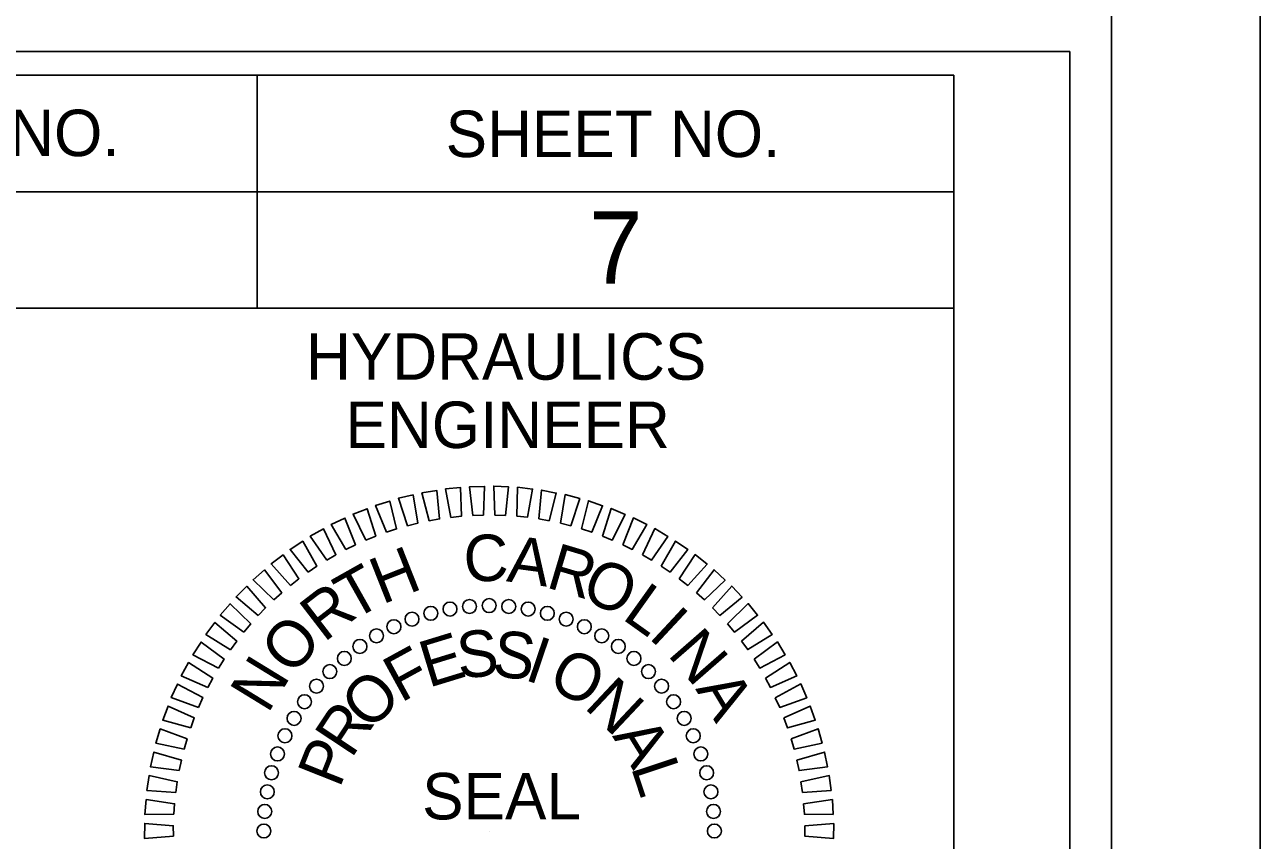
# Model space of a CAD drawing. Extents: x 1633303 to 1635397, y 883210 to 885302.
# Drawn here: x 1635263.8 to 1635396.9, y 884890.3 to 884978 of the extents above; entities that cross this region are included whole.
import ezdxf

# ---------------------------------------------------------------- set-up
doc = ezdxf.new("R2010")
doc.units = 0
for name, color, linetype in [('Sheet Data Field CELL', 7, 'Continuous'), ('Sheet PE Seal Cell', 7, 'Continuous'), ('Sheet Plot Border Inside CELL', 7, 'Continuous'), ('Sheet Plot Border Outside CELL', 7, 'Continuous'), ('Sheet Profile CELL', 7, 'Continuous'), ('Stewart Plot Border Xerox6279 and LJ5000', 7, 'Continuous')]:
    doc.layers.add(name, color=color, linetype=linetype)

msp = doc.modelspace()

# ---------------------------------------------------------------- linework, layer by layer
at = {"layer": 'Sheet PE Seal Cell'}
msp.add_line((1635313.84, 884891.31), (1635313.84, 884891.31), dxfattribs=at)
for points in [[(1635309.72, 884925.05), (1635309.16, 884928.12), (1635310.77, 884928.26), (1635310.85, 884925.17)], [(1635312.08, 884925.25), (1635311.74, 884928.35), (1635313.35, 884928.38), (1635313.22, 884925.3)], [(1635314.45, 884925.29), (1635314.33, 884928.41), (1635315.94, 884928.33), (1635315.6, 884925.26)], [(1635316.82, 884925.17), (1635316.91, 884928.29), (1635318.52, 884928.09), (1635317.96, 884925.06)], [(1635302.79, 884923.45), (1635301.61, 884926.34), (1635303.15, 884926.81), (1635303.88, 884923.81)], [(1635305.06, 884924.15), (1635304.08, 884927.11), (1635305.66, 884927.47), (1635306.17, 884924.43)], [(1635307.38, 884924.68), (1635306.6, 884927.7), (1635308.2, 884927.95), (1635308.5, 884924.88)], [(1635319.18, 884924.88), (1635319.49, 884927.98), (1635321.07, 884927.67), (1635320.3, 884924.69)], [(1635321.51, 884924.42), (1635322.03, 884927.5), (1635323.59, 884927.08), (1635322.62, 884924.15)], [(1635323.8, 884923.81), (1635324.53, 884926.84), (1635326.06, 884926.31), (1635324.89, 884923.46)], [(1635300.58, 884922.61), (1635299.19, 884925.4), (1635300.7, 884925.98), (1635301.63, 884923.04)], [(1635326.04, 884923.03), (1635326.99, 884926.01), (1635328.47, 884925.37), (1635327.1, 884922.61)], [(1635298.43, 884921.6), (1635296.85, 884924.3), (1635298.32, 884924.98), (1635299.45, 884922.11)], [(1635328.22, 884922.1), (1635329.38, 884925), (1635330.82, 884924.27), (1635329.25, 884921.61)], [(1635296.35, 884920.46), (1635294.59, 884923.03), (1635296, 884923.82), (1635297.34, 884921.03)], [(1635330.34, 884921.03), (1635331.69, 884923.84), (1635333.07, 884923.01), (1635331.33, 884920.46)], [(1635294.36, 884919.16), (1635292.42, 884921.61), (1635293.78, 884922.49), (1635295.3, 884919.81)], [(1635332.37, 884919.8), (1635333.91, 884922.51), (1635335.24, 884921.59), (1635333.32, 884919.17)], [(1635292.47, 884917.74), (1635290.36, 884920.04), (1635291.65, 884921.02), (1635293.36, 884918.45)], [(1635334.31, 884918.44), (1635336.04, 884921.04), (1635337.3, 884920.02), (1635335.22, 884917.74)], [(1635290.67, 884916.18), (1635288.42, 884918.34), (1635289.64, 884919.4), (1635291.52, 884916.95)], [(1635336.16, 884916.95), (1635338.06, 884919.42), (1635339.24, 884918.31), (1635337.01, 884916.19)], [(1635288.99, 884914.51), (1635286.59, 884916.5), (1635287.74, 884917.64), (1635289.78, 884915.33)], [(1635337.89, 884915.33), (1635339.96, 884917.66), (1635341.07, 884916.48), (1635338.69, 884914.51)], [(1635287.44, 884912.72), (1635284.9, 884914.54), (1635285.96, 884915.76), (1635288.17, 884913.6)], [(1635339.51, 884913.59), (1635341.74, 884915.77), (1635342.75, 884914.52), (1635340.25, 884912.72)], [(1635286.01, 884910.82), (1635283.35, 884912.46), (1635284.32, 884913.75), (1635286.67, 884911.75)], [(1635341, 884911.75), (1635343.38, 884913.77), (1635344.3, 884912.44), (1635341.68, 884910.83)], [(1635284.71, 884908.83), (1635281.95, 884910.28), (1635282.83, 884911.64), (1635285.31, 884909.81)], [(1635342.36, 884909.8), (1635344.87, 884911.65), (1635345.7, 884910.27), (1635342.97, 884908.84)], [(1635283.56, 884906.76), (1635280.7, 884908.01), (1635281.49, 884909.43), (1635284.09, 884907.77)], [(1635343.58, 884907.77), (1635346.21, 884909.44), (1635346.95, 884908), (1635344.12, 884906.76)], [(1635282.56, 884904.61), (1635279.62, 884905.66), (1635280.3, 884907.12), (1635283.02, 884905.66)], [(1635344.65, 884905.65), (1635347.4, 884907.13), (1635348.03, 884905.65), (1635345.13, 884904.61)], [(1635281.71, 884902.4), (1635278.7, 884903.24), (1635279.28, 884904.75), (1635282.09, 884903.47)], [(1635345.58, 884903.47), (1635348.42, 884904.75), (1635348.95, 884903.23), (1635345.98, 884902.4)], [(1635281.01, 884900.13), (1635277.96, 884900.76), (1635278.43, 884902.3), (1635281.32, 884901.23)], [(1635346.35, 884901.22), (1635349.28, 884902.31), (1635349.69, 884900.75), (1635346.67, 884900.13)], [(1635280.48, 884897.82), (1635277.38, 884898.23), (1635277.75, 884899.81), (1635280.71, 884898.94)], [(1635346.96, 884898.93), (1635349.96, 884899.81), (1635350.27, 884898.22), (1635347.21, 884897.82)], [(1635280.1, 884895.47), (1635276.99, 884895.67), (1635277.24, 884897.27), (1635280.26, 884896.61)], [(1635347.41, 884896.6), (1635350.46, 884897.27), (1635350.66, 884895.67), (1635347.58, 884895.47)], [(1635279.9, 884893.11), (1635276.77, 884893.09), (1635276.92, 884894.7), (1635279.97, 884894.25)], [(1635347.7, 884894.25), (1635350.79, 884894.7), (1635350.87, 884893.09), (1635347.79, 884893.11)], [(1635279.85, 884890.74), (1635276.74, 884890.5), (1635276.77, 884892.12), (1635279.84, 884891.88)], [(1635347.82, 884891.88), (1635350.94, 884892.11), (1635350.91, 884890.5), (1635347.83, 884890.74)]]:
    msp.add_lwpolyline(points, close=True, dxfattribs=at)
for centre in [(1635311.72, 884915.47), (1635313.84, 884915.56), (1635315.95, 884915.47), (1635305.54, 884914.1), (1635307.56, 884914.73), (1635309.63, 884915.19), (1635318.05, 884915.19), (1635320.11, 884914.73), (1635322.13, 884914.1), (1635303.59, 884913.29), (1635324.09, 884913.29), (1635301.71, 884912.31), (1635325.96, 884912.31), (1635299.93, 884911.17), (1635327.75, 884911.17), (1635298.25, 884909.88), (1635329.43, 884909.88), (1635296.69, 884908.46), (1635330.99, 884908.46), (1635295.26, 884906.9), (1635332.41, 884906.9), (1635293.97, 884905.22), (1635333.7, 884905.22), (1635292.84, 884903.43), (1635334.84, 884903.43), (1635291.86, 884901.56), (1635335.82, 884901.56), (1635291.05, 884899.6), (1635336.63, 884899.6), (1635290.41, 884897.58), (1635337.26, 884897.58), (1635289.96, 884895.52), (1635337.72, 884895.52), (1635289.68, 884893.42), (1635338, 884893.42), (1635289.59, 884891.31), (1635338.09, 884891.31)]:
    msp.add_circle(centre, 0.75, dxfattribs=at)
at = {"layer": 'Sheet Plot Border Inside CELL'}
msp.add_lwpolyline([(1635376.36, 884975.16), (1633709.86, 884975.16), (1633709.86, 883920.06), (1635376.36, 883920.06)], close=True, dxfattribs=at)
at = {"layer": 'Sheet Plot Border Outside CELL'}
msp.add_lwpolyline([(1635380.86, 884997.61), (1633696.86, 884997.61), (1633696.86, 883897.61), (1635380.86, 883897.61)], close=True, dxfattribs=at)
at = {"layer": 'Sheet Profile CELL'}
for p, q in [((1635288.86, 884972.56), (1635288.86, 884947.56)), ((1635163.81, 884960.06), (1635363.86, 884960.06)), ((1635263.86, 884947.56), (1635363.86, 884947.56)), ((1635363.86, 884947.56), (1635363.86, 884835.06))]:
    msp.add_line(p, q, dxfattribs=at)
for points in [[(1635363.86, 884972.61), (1633863.86, 884972.61), (1633863.86, 883922.61), (1635363.86, 883922.61)], [(1635163.81, 884972.61), (1635363.86, 884972.61), (1635363.86, 884947.56), (1635163.81, 884947.56)]]:
    msp.add_lwpolyline(points, close=True, dxfattribs=at)
at = {"layer": 'Stewart Plot Border Xerox6279 and LJ5000'}
msp.add_lwpolyline([(1633696.86, 883897.61), (1635396.86, 883897.61), (1635396.86, 884997.61), (1633696.86, 884997.61)], close=True, dxfattribs=at)

# ---------------------------------------------------------------- texts
at = {"layer": 'Sheet Data Field CELL'}
msp.add_text('7', height=7.75, dxfattribs=at).set_placement((1635324.6, 884950.21))
at = {"layer": 'Sheet PE Seal Cell'}
for s, rotation, p in [('C', 1.9618, (1635311.17, 884918.11)), ('A', 352.4568, (1635315.63, 884918.18)), ('H', 21.601, (1635302.32, 884915.65)), ('R', 343.4093, (1635319.83, 884917.56)), ('T', 29.3903, (1635299.12, 884913.87)), ('O', 335.2006, (1635323.52, 884916.44)), ('R', 37.5989, (1635296.05, 884911.53)), ('L', 324.4755, (1635328.03, 884914.2)), ('I', 317.0103, (1635330.88, 884912.16)), ('O', 48.3241, (1635292.6, 884907.87)), ('E', 16.986, (1635307.31, 884906.7)), ('S', 5.2237, (1635310.58, 884907.7)), ('S', 353.2648, (1635314.05, 884908.02)), ('I', 341.3058, (1635317.51, 884907.62)), ('N', 311.0704, (1635332.95, 884910.28)), ('F', 28.6639, (1635304.33, 884905.06)), ('N', 58.5345, (1635290, 884903.84)), ('O', 332.5504, (1635319.95, 884906.87)), ('O', 44.4727, (1635300.94, 884901.95)), ('N', 316.7416, (1635323.96, 884904.61)), ('A', 300.8599, (1635336.01, 884906.6)), ('R', 56.5721, (1635299, 884899.01)), ('A', 301.6915, (1635327.06, 884901.53)), ('P', 68.3344, (1635297.74, 884895.82)), ('L', 288.3556, (1635329.07, 884898.2))]:
    msp.add_text(s, height=5, rotation=rotation, dxfattribs=at).set_placement(p)
msp.add_text('SEAL', height=5, dxfattribs=at).set_placement((1635306.63, 884892.56))
at = {"layer": 'Sheet Profile CELL'}
for s, height, p in [('PROJECT REFERENCE NO.', 5.0001, (1635186.01, 884963.91)), ('SHEET NO.', 5, (1635309.16, 884963.81)), ('HYDRAULICS', 5, (1635294.13, 884939.86)), ('ENGINEER', 5, (1635298.38, 884932.51))]:
    msp.add_text(s, height=height, dxfattribs=at).set_placement(p)

doc.saveas('drawing.dxf')
